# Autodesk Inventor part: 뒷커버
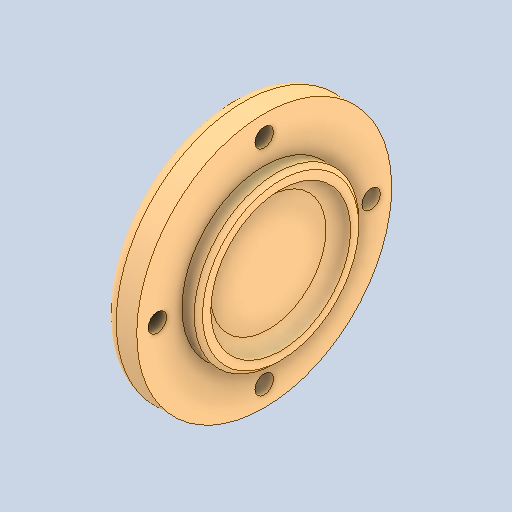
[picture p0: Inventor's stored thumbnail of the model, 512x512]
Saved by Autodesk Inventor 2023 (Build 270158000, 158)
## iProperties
Created: 2024-09
Part Number: 뒷커버
Material: 알루미늄 6061
Document SubType Name: Modeling
Designer: home
Density: 2.7 g/cm^3
Appearance: 기본값
Author: jhkim
Sending System: Autodesk Inventor 2025
Preprocessor: ST-DEVELOPER v20
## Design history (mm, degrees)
feature "솔리드1"
node "솔리드2"
